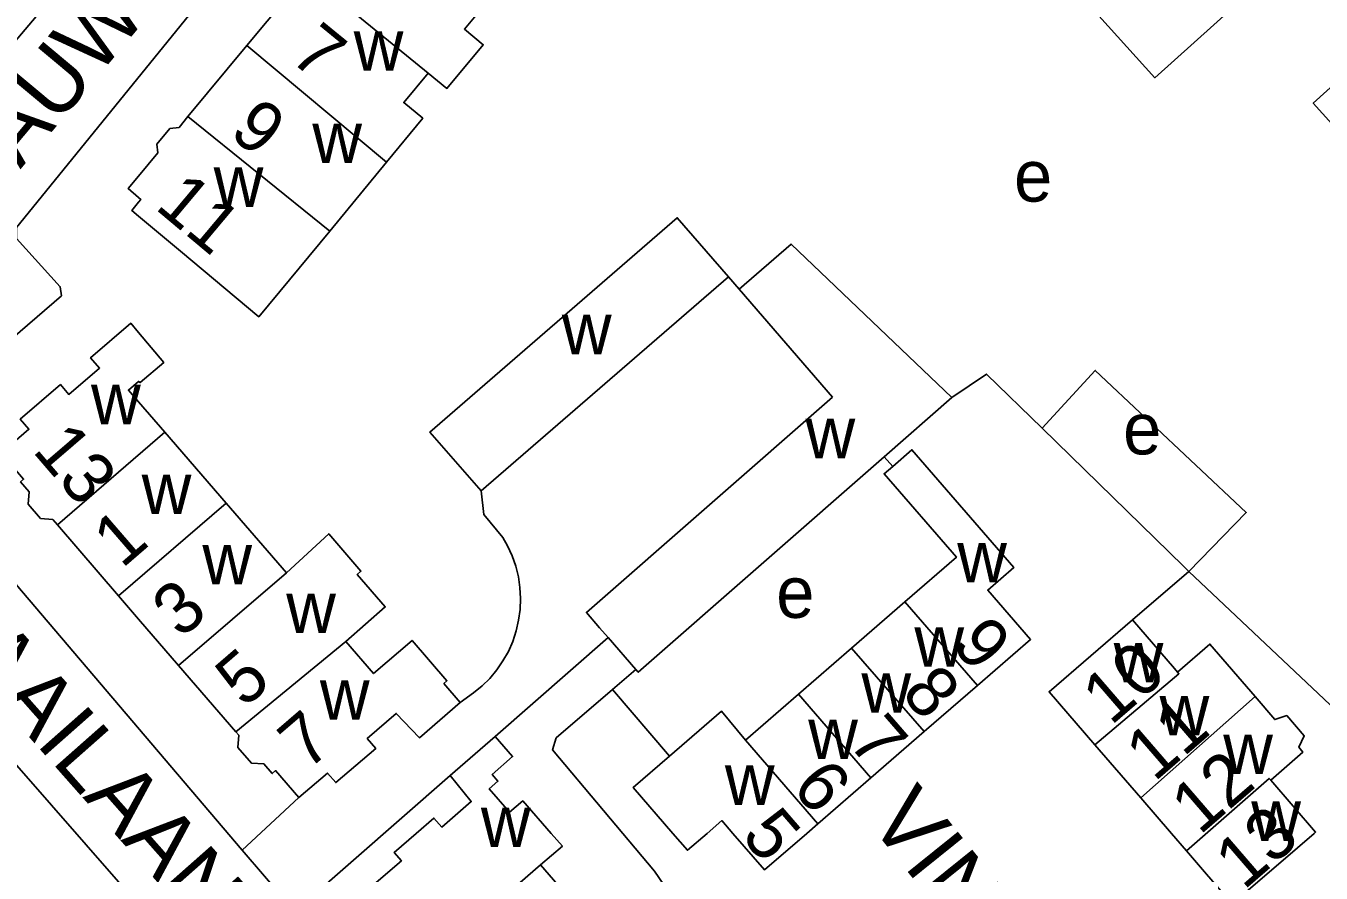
# Model space of a CAD drawing. Extents: x 161775 to 163181, y 382878 to 383925.
# Drawn here: x 162491.2 to 162592, y 383496.9 to 383562.8 of the extents above; entities that cross this region are included whole.
import ezdxf

# ---------------------------------------------------------------- set-up
doc = ezdxf.new("R2010")
doc.units = 0
for name, color, linetype in [('BLT_Basislijn', 7, 'Continuous'), ('BLT_Bebouwing', 7, 'Continuous'), ('BLT_Centroide', 7, 'Continuous'), ('BLT_Huisnummer', 7, 'Continuous'), ('BLT_Huisnummer_ tussenligend', 7, 'Continuous'), ('BLT_Onderverdeling_panden', 7, 'Continuous'), ('BLT_Straatnaam', 7, 'Continuous')]:
    doc.layers.add(name, color=color, linetype=linetype)

msp = doc.modelspace()

# ---------------------------------------------------------------- linework, layer by layer
at = {"layer": 'BLT_Basislijn'}
for p, q in [((162494.16, 383566.07), (162488.99, 383560.01)), ((162545.87, 383543.31), (162546.71, 383542.34)), ((162480.94, 383530.56), (162508.06, 383498.69)), ((162558, 383529.31), (162558.66, 383528.56)), ((162577.3, 383516.61), (162581.68, 383520.39)), ((162527.73, 383507.54), (162536.51, 383515.25)), ((162538.67, 383512.76), (162536.86, 383511.2)), ((162541.28, 383506.01), (162536.86, 383511.2)), ((162512.15, 383493.92), (162524.24, 383504.51)), ((162508.06, 383498.69), (162512.46, 383502.78)), ((162508.06, 383498.69), (162511.52, 383494.65))]:
    msp.add_line(p, q, dxfattribs=at)
for points in [[(162512.31, 383574.02), (162490.5, 383547.14), (162490.5, 383546.29), (162493.91, 383542.53), (162494, 383541.83), (162480.94, 383530.56)], [(162570.27, 383531.52), (162565.94, 383535.74), (162563.26, 383533.91)], [(162570.27, 383531.52), (162574.4, 383536.02), (162586.15, 383524.98), (162581.68, 383520.39)], [(162581.68, 383520.39), (162581.26, 383520.79), (162570.27, 383531.52)], [(162528.33, 383523.02), (162526.85, 383524.81), (162526.64, 383526.65)], [(162525.02, 383510.18), (162526.05, 383510.93), (162526.71, 383511.47), (162527.31, 383512.06), (162527.86, 383512.72), (162528.34, 383513.42), (162528.76, 383514.16), (162529.1, 383514.94), (162529.37, 383515.75), (162529.56, 383516.58), (162529.67, 383517.42), (162529.71, 383518.27), (162529.66, 383519.12), (162529.54, 383519.97), (162529.33, 383520.79), (162529.05, 383521.6), (162528.7, 383522.37), (162528.33, 383523.02)], [(162476.85, 383520.93), (162504.19, 383489.63), (162504.09, 383488.84), (162502.12, 383486.99), (162474.34, 383462.96)], [(162581.68, 383520.39), (162600, 383503.11), (162600.97, 383502.13)], [(162536.86, 383511.2), (162532.47, 383507.43), (162532.2, 383506.5), (162540.12, 383497.07), (162543.14, 383492.66)]]:
    msp.add_lwpolyline(points, dxfattribs=at)
at = {"layer": 'BLT_Bebouwing'}
for p, q in [((162513.05, 383566.89), (162508.42, 383561.3)), ((162508.42, 383561.3), (162503.84, 383555.77)), ((162545.87, 383543.31), (162526.64, 383526.65)), ((162553.98, 383533.95), (162546.71, 383542.34)), ((162558, 383529.31), (162563.26, 383533.91)), ((162506.81, 383525.69), (162502.03, 383531.22)), ((162511.49, 383520.28), (162506.81, 383525.69)), ((162493.69, 383524.01), (162498.44, 383518.48)), ((162555.46, 383514.42), (162559.6, 383518.01)), ((162535.86, 383516), (162536.51, 383515.25)), ((162536.51, 383515.25), (162538.67, 383512.76)), ((162551.33, 383510.83), (162555.46, 383514.42)), ((162503.11, 383513.07), (162507.56, 383507.9)), ((162523.74, 383511.67), (162525.02, 383510.18)), ((162561.1, 383507.92), (162565.24, 383511.5)), ((162547.19, 383507.25), (162551.33, 383510.83)), ((162527.73, 383507.54), (162524.24, 383504.51)), ((162556.96, 383504.33), (162561.1, 383507.92)), ((162577.94, 383502.76), (162574.38, 383506.89)), ((162552.83, 383500.74), (162556.96, 383504.33)), ((162585.06, 383494.51), (162581.5, 383498.64))]:
    msp.add_line(p, q, dxfattribs=at)
for points in [[(162583.96, 383574.02), (162578.69, 383569.28), (162575.34, 383573), (162571.62, 383569.65), (162570.32, 383568.47), (162579.04, 383558.79), (162590, 383568.67), (162591.94, 383566.52)], [(162522.51, 383559.16), (162523.98, 383557.96), (162526.8, 383561.37), (162525.34, 383562.58), (162527.42, 383565.08), (162526.19, 383566.1), (162526.61, 383566.6), (162523.2, 383569.43), (162519.35, 383572.62), (162518.61, 383571.73), (162517.71, 383572.47), (162515.33, 383569.6), (162514.49, 383569.52), (162513.42, 383568.23), (162513.65, 383567.61), (162513.05, 383566.89)], [(162596.8, 383545.1), (162593.38, 383548.9), (162596.21, 383551.45), (162591.36, 383556.83), (162597.18, 383562.08)], [(162519.27, 383552.23), (162522.1, 383555.65), (162520.62, 383556.87), (162522.51, 383559.16)], [(162514.88, 383546.86), (162509.35, 383540.2), (162503.27, 383545.29), (162500, 383548.03), (162499.47, 383548.47), (162500, 383549.11), (162500.18, 383549.32), (162500, 383549.47), (162499.19, 383550.17), (162500, 383551.15), (162501.49, 383552.95), (162501.43, 383553.64), (162502.44, 383554.86), (162503.15, 383554.93), (162503.84, 383555.77)], [(162514.88, 383546.86), (162519.27, 383552.23)], [(162526.64, 383526.65), (162522.66, 383531.23), (162541.89, 383547.9), (162545.87, 383543.31)], [(162546.71, 383542.34), (162550.75, 383545.85), (162557.62, 383539.29), (162563.26, 383533.91)], [(162502.03, 383531.22), (162500, 383533.57), (162499.21, 383534.49), (162500, 383535.17), (162500.13, 383535.08), (162501.95, 383536.64), (162500, 383538.98), (162499.39, 383539.69), (162496.27, 383537.01), (162496.96, 383536.21), (162494.57, 383534.15), (162493.92, 383534.92), (162490.79, 383532.23), (162491.47, 383531.44), (162489.3, 383529.58), (162491.05, 383527.55), (162490.82, 383527.36), (162491.5, 383526.57), (162491.42, 383525.61), (162492.37, 383524.5), (162493.32, 383524.43), (162493.69, 383524.01)], [(162553.98, 383533.95), (162534.83, 383517.19), (162535.86, 383516)], [(162538.67, 383512.76), (162538.86, 383512.54), (162558, 383529.31)], [(162565.24, 383511.5), (162569.37, 383515.09), (162566.05, 383518.93), (162568.08, 383520.69), (162560.14, 383529.85), (162558.66, 383528.56)], [(162559.6, 383518.01), (162563.61, 383521.48), (162557.98, 383527.98), (162558.66, 383528.56)], [(162516.12, 383514.92), (162519.18, 383517.62), (162517, 383520.15), (162517.29, 383520.4), (162514.79, 383523.31), (162511.49, 383520.28)], [(162498.44, 383518.48), (162499.99, 383516.67), (162503.11, 383513.07)], [(162574.38, 383506.89), (162570.82, 383511.02), (162577.3, 383516.61)], [(162577.3, 383516.61), (162580.57, 383512.82), (162580.81, 383512.55)], [(162523.74, 383511.67), (162523.98, 383511.87), (162521.27, 383515.01), (162518.27, 383512.43), (162516.12, 383514.92)], [(162580.81, 383512.55), (162583.33, 383514.73), (162586.84, 383510.64)], [(162525.02, 383510.18), (162521.84, 383507.44), (162520.04, 383509.33), (162517.78, 383507.38), (162518.44, 383506.61), (162515.33, 383503.95), (162514.69, 383504.69), (162512.46, 383502.78)], [(162586.84, 383510.64), (162588.37, 383508.86), (162589.3, 383509.16), (162590.66, 383507.59), (162590.24, 383506.7), (162590.56, 383506.32), (162588.05, 383504.15)], [(162541.28, 383506.01), (162545.33, 383509.52), (162547.19, 383507.25)], [(162507.56, 383507.9), (162507.79, 383507.63), (162507.72, 383506.69), (162508.77, 383505.47), (162509.75, 383505.4), (162510.39, 383504.65), (162510.66, 383504.88), (162512.46, 383502.78)], [(162531.27, 383497.55), (162532.96, 383499.01), (162532.09, 383500), (162529.88, 383502.53), (162528.85, 383501.64), (162527.27, 383503.47), (162527.95, 383504.06), (162527.5, 383504.59), (162529.09, 383505.97), (162527.73, 383507.54)], [(162552.83, 383500.74), (162551.97, 383500), (162548.69, 383497.16), (162546.23, 383500), (162545.36, 383501), (162544.21, 383500), (162542.69, 383498.69), (162541.56, 383500), (162538.46, 383503.57), (162541.28, 383506.01)], [(162524.24, 383504.51), (162525.87, 383502.48), (162523.58, 383500.49), (162522.97, 383501.19), (162521.59, 383500), (162519.88, 383498.52), (162520.44, 383497.87), (162518.12, 383495.86), (162520.4, 383493.22), (162520.33, 383492.26), (162521.38, 383491.05), (162522.39, 383490.97), (162522.93, 383490.34)], [(162588.05, 383504.15), (162591.54, 383500.1), (162591.43, 383500), (162588.85, 383497.77), (162585.06, 383494.51)], [(162581.5, 383498.64), (162580.33, 383500), (162577.94, 383502.76)], [(162522.93, 383490.34), (162527.56, 383484.99), (162529.82, 383486.94), (162530.41, 383486.25), (162533.66, 383489.05), (162533.12, 383489.66), (162535.98, 383492.13), (162536.32, 383491.73), (162537.63, 383492.87), (162534.95, 383495.97), (162533.63, 383494.82), (162531.27, 383497.55)]]:
    msp.add_lwpolyline(points, dxfattribs=at)
at = {"layer": 'BLT_Onderverdeling_panden'}
for p, q in [((162522.51, 383559.16), (162513.05, 383566.89)), ((162519.27, 383552.23), (162508.42, 383561.3)), ((162514.88, 383546.86), (162503.84, 383555.77)), ((162493.69, 383524.01), (162502.03, 383531.22)), ((162498.44, 383518.48), (162506.81, 383525.69)), ((162503.11, 383513.07), (162511.49, 383520.28)), ((162565.24, 383511.5), (162559.6, 383518.01)), ((162507.56, 383507.9), (162516.12, 383514.92)), ((162561.1, 383507.92), (162555.46, 383514.42)), ((162556.96, 383504.33), (162551.33, 383510.83)), ((162552.83, 383500.74), (162547.19, 383507.25)), ((162522.93, 383490.34), (162531.27, 383497.55))]:
    msp.add_line(p, q, dxfattribs=at)
for points in [[(162574.38, 383506.89), (162580.91, 383512.42), (162580.81, 383512.55)], [(162577.94, 383502.76), (162586.84, 383510.64)], [(162581.5, 383498.64), (162587.93, 383504.28), (162588.05, 383504.15)]]:
    msp.add_lwpolyline(points, dxfattribs=at)

# ---------------------------------------------------------------- texts
at = {"layer": 'BLT_Centroide'}
for s, p in [('w', (162516.73, 383559.34)), ('w', (162513.51, 383552.16)), ('w', (162505.84, 383548.75)), ('e', (162568.09, 383549.16)), ('w', (162532.92, 383537.28)), ('w', (162496.3, 383531.84)), ('e', (162576.57, 383529.49)), ('w', (162551.87, 383529.19)), ('w', (162500.24, 383524.84)), ('w', (162504.96, 383519.38)), ('w', (162563.67, 383519.53)), ('e', (162549.59, 383516.77)), ('w', (162511.48, 383515.59)), ('w', (162560.34, 383512.97)), ('w', (162575.84, 383511.75)), ('w', (162556.22, 383509.38)), ('w', (162514.1, 383508.84)), ('w', (162579.41, 383507.62)), ('w', (162552.08, 383505.78)), ('w', (162584.36, 383504.62)), ('w', (162545.6, 383502.22)), ('w', (162586.54, 383499.41)), ('w', (162526.62, 383498.94))]:
    msp.add_text(s, height=4, dxfattribs=at).set_placement(p)
at = {"layer": 'BLT_Huisnummer'}
for s, rotation, p in [('11', 320.0274, (162501.18, 383548.66)), ('13', 310.678, (162491.67, 383529.76)), ('1', 40.8283, (162498.7, 383520.55)), ('9', 310.9191, (162563.15, 383514.61)), ('5', 40.8283, (162508.21, 383509.69)), ('10', 40.7741, (162575.62, 383508.33)), ('7', 40.6741, (162513.11, 383504.82)), ('7', 310.9184, (162555.09, 383507.01)), ('5', 310.8298, (162546.79, 383499.75)), ('13', 40.7504, (162585.95, 383495.53))]:
    msp.add_text(s, height=4, rotation=rotation, dxfattribs=at).set_placement(p)
at = {"layer": 'BLT_Huisnummer_ tussenligend'}
for s, rotation, p in [('7', 320.7437, (162511.63, 383560.23)), ('9', 320.7437, (162506.94, 383554.36)), ('3', 40.8283, (162503.29, 383515.09)), ('8', 310.9191, (162559.21, 383510.85)), ('11', 40.7792, (162579, 383503.95)), ('12', 40.7748, (162582.52, 383499.81)), ('6', 310.9184, (162550.71, 383503.52))]:
    msp.add_text(s, height=4, rotation=rotation, dxfattribs=at).set_placement(p)
at = {"layer": 'BLT_Straatnaam'}
for s, height, rotation, p in [('PELIKAANLAAN', 4.9999, 311.9288, (162585.82, 383590.8)), ('PAUWLAAN', 5, 50.1275, (162487.94, 383548.23)), ('GAAILAAN', 5, 311.4755, (162482.57, 383517.57)), ('VINKENHOFJE', 5, 308.8135, (162556.64, 383500.95))]:
    msp.add_text(s, height=height, rotation=rotation, dxfattribs=at).set_placement(p)

doc.saveas('drawing.dxf')
